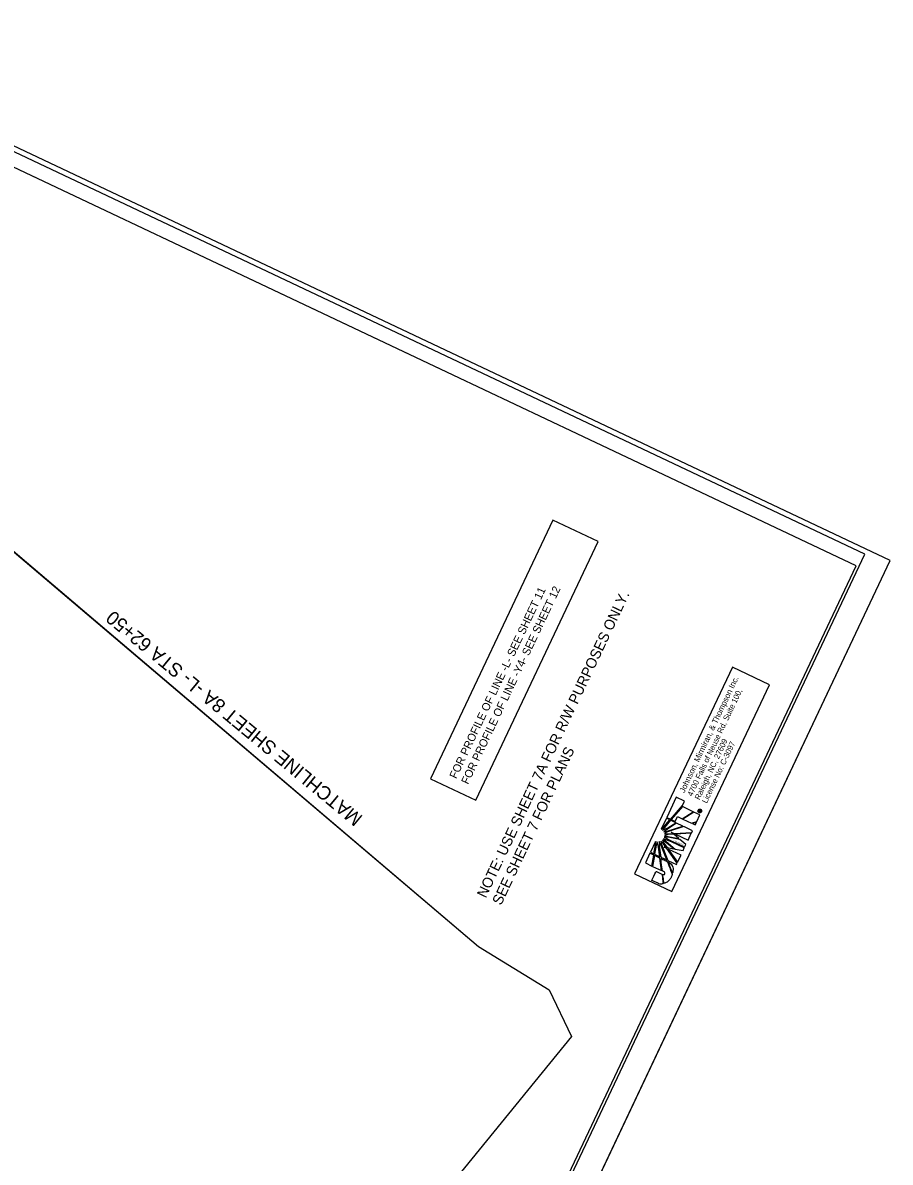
# Model space of a CAD drawing. Extents: x 556536 to 558250, y 505355 to 507347.
# Drawn here: x 557491 to 558250, y 506351 to 507347 of the extents above; entities that cross this region are included whole.
import ezdxf

# ---------------------------------------------------------------- set-up
doc = ezdxf.new("R2010")
doc.units = 0
for name, color, linetype in [('Matchline', 7, 'Continuous'), ('Matchline Text', 7, 'Continuous'), ('Prop Horizontal Alignment Curve and Spiral Data', 7, 'Continuous'), ('Prop Horizontal Alignment Direction Label', 7, 'Continuous'), ('Prop SS Cut Line', 7, 'Continuous'), ('Prop SS Fill Line', 7, 'Continuous'), ('Scratch_Level_9', 7, 'Continuous'), ('Sheet Clip Boundary CELL', 7, 'Continuous')]:
    doc.layers.add(name, color=color, linetype=linetype)

msp = doc.modelspace()

# ---------------------------------------------------------------- linework, layer by layer
at = {"layer": 'Matchline'}
for p, q in [((557395.12, 506959.79), (557889.73, 506539.36)), ((558062.8, 506670.04), (558054.41, 506652.24)), ((558070.09, 506666.6), (558062.8, 506670.04)), ((558057.77, 506650.65), (558068.31, 506662.82)), ((558068.21, 506661.77), (558058.28, 506650.42)), ((558077.55, 506657.36), (558068.21, 506661.77)), ((558068.31, 506662.82), (558070.09, 506666.6)), ((558081.91, 506658.68), (558082.18, 506658.56)), ((558082.18, 506658.56), (558081.91, 506658.68)), ((558082.42, 506657.79), (558082.67, 506658.32)), ((558082.67, 506658.32), (558082.71, 506658.41)), ((558082.67, 506658.32), (558082.92, 506658.21)), ((558082.92, 506658.21), (558082.67, 506658.32)), ((558082.92, 506658.21), (558082.81, 506657.97)), ((558082.81, 506657.97), (558083.11, 506657.83)), ((558082.93, 506658.24), (558082.92, 506658.21)), ((558083.11, 506657.83), (558083.22, 506658.06)), ((558083.22, 506658.06), (558083.23, 506658.07)), ((558083.22, 506658.06), (558083.46, 506657.95)), ((558083.46, 506657.95), (558083.22, 506658.06)), ((558083.46, 506657.95), (558083.35, 506657.72)), ((558083.47, 506657.96), (558083.46, 506657.95)), ((558054.14, 506651.56), (558049.67, 506642.19)), ((558051.91, 506644.04), (558057.18, 506650.13)), ((558057.83, 506649.83), (558052.41, 506643.52)), ((558057.18, 506650.13), (558054.14, 506651.56)), ((558054.41, 506652.24), (558057.67, 506650.7)), ((558057.67, 506650.7), (558057.77, 506650.65)), ((558062.29, 506647.65), (558057.83, 506649.83)), ((558058.28, 506650.42), (558058.33, 506650.39)), ((558058.33, 506650.39), (558061.74, 506648.78)), ((558061.74, 506648.78), (558063.79, 506653.13)), ((558063.79, 506653.13), (558067.86, 506651.21)), ((558067.86, 506651.21), (558077.55, 506657.36)), ((558078.21, 506657.05), (558068.55, 506650.88)), ((558068.55, 506650.88), (558076.13, 506647.31)), ((558076.13, 506647.31), (558080.76, 506648.83)), ((558080.36, 506648), (558076.95, 506646.92)), ((558083.46, 506654.58), (558078.21, 506657.05)), ((558079.33, 506645.8), (558080.36, 506648)), ((558080.76, 506648.83), (558083.46, 506654.58)), ((558083.72, 506657.18), (558082.42, 506657.79)), ((558083.35, 506657.72), (558083.85, 506657.48)), ((558083.85, 506657.48), (558083.72, 506657.18)), ((558084.47, 506657.47), (558084.48, 506657.49)), ((558084.47, 506657.47), (558084.75, 506657.34)), ((558084.75, 506657.34), (558084.47, 506657.47)), ((558084.76, 506657.35), (558084.75, 506657.34)), ((558049.67, 506642.19), (558051.91, 506644.04)), ((558052.41, 506643.52), (558050.84, 506641.06)), ((558050.84, 506641.06), (558055.42, 506643.24)), ((558054.98, 506642.2), (558051.81, 506639.7)), ((558051.81, 506639.7), (558054.91, 506640.24)), ((558055.15, 506639.66), (558052.36, 506638.23)), ((558052.36, 506638.23), (558055.56, 506637.98)), ((558054.91, 506640.24), (558068.46, 506644.74)), ((558063.04, 506647.3), (558054.98, 506642.2)), ((558069.34, 506644.33), (558055.15, 506639.66)), ((558055.42, 506643.24), (558062.29, 506647.65)), ((558055.56, 506637.98), (558059.78, 506638.21)), ((558059.78, 506638.21), (558058.31, 506639.44)), ((558058.31, 506639.44), (558060.78, 506638.27)), ((558060.78, 506638.27), (558076.24, 506639.25)), ((558075.87, 506638.57), (558062, 506637.7)), ((558068.46, 506644.74), (558063.04, 506647.3)), ((558076.94, 506640.74), (558069.34, 506644.33)), ((558073.01, 506632.51), (558075.87, 506638.57)), ((558076.24, 506639.25), (558076.94, 506640.74)), ((558076.95, 506646.92), (558079.33, 506645.8)), ((558044.58, 506631.41), (558040.09, 506621.88)), ((558043.12, 506620.45), (558044.51, 506628.47)), ((558045.17, 506628.16), (558043.78, 506620.14)), ((558044.51, 506628.47), (558044.58, 506631.41)), ((558046.14, 506631.08), (558045.17, 506628.16)), ((558047.34, 506626.23), (558046.14, 506631.08)), ((558049.3, 506628.45), (558047.78, 506631.16)), ((558047.78, 506631.16), (558047.89, 506627.17)), ((558049.26, 506631.66), (558049.93, 506628.59)), ((558051.49, 506629.35), (558049.26, 506631.66)), ((558054.38, 506615.14), (558049.3, 506628.45)), ((558049.93, 506628.59), (558055.28, 506614.72)), ((558050.59, 506632.52), (558051.95, 506629.83)), ((558053.09, 506631.05), (558050.59, 506632.52)), ((558053.88, 506626.05), (558051.49, 506629.35)), ((558058.48, 506630.95), (558051.63, 506633.74)), ((558051.63, 506633.74), (558053.79, 506631.3)), ((558051.95, 506629.83), (558054.78, 506625.91)), ((558052.28, 506635.14), (558058.76, 506631.56)), ((558055.52, 506634.98), (558052.28, 506635.14)), ((558055.47, 506637.29), (558052.55, 506636.67)), ((558052.55, 506636.67), (558055.39, 506635.67)), ((558060.51, 506624.87), (558053.09, 506631.05)), ((558053.79, 506631.3), (558061.82, 506624.6)), ((558055.39, 506635.67), (558064.97, 506633.83)), ((558060.47, 506637.61), (558055.47, 506637.29)), ((558065.96, 506633.03), (558055.52, 506634.98)), ((558069.77, 506625.63), (558058.48, 506630.95)), ((558058.76, 506631.56), (558070.05, 506626.23)), ((558064.97, 506633.83), (558060.47, 506637.61)), ((558062, 506637.7), (558073.01, 506632.51)), ((558071.16, 506628.58), (558065.96, 506633.03)), ((558070.05, 506626.23), (558071.16, 506628.58)), ((558039.72, 506620.98), (558035.72, 506612.51)), ((558042.99, 506619.44), (558039.72, 506620.98)), ((558040.09, 506621.88), (558043.12, 506620.45)), ((558041.34, 506609.86), (558042.99, 506619.44)), ((558043.6, 506619.15), (558041.98, 506609.56)), ((558048.51, 506616.84), (558043.6, 506619.15)), ((558043.78, 506620.14), (558048.36, 506617.98)), ((558048.36, 506617.98), (558047.34, 506626.23)), ((558047.89, 506627.17), (558049.1, 506617.63)), ((558054.38, 506625.3), (558052.14, 506626.36)), ((558052.14, 506626.36), (558053.88, 506626.05)), ((558063.62, 506612.49), (558054.38, 506625.3)), ((558054.78, 506625.91), (558060.51, 506624.87)), ((558066.91, 506619.46), (558055.59, 506624.73)), ((558055.59, 506624.73), (558063.93, 506613.15)), ((558061.82, 506624.6), (558068.67, 506623.31)), ((558063.93, 506613.15), (558066.91, 506619.46)), ((558068.67, 506623.31), (558069.77, 506625.63)), ((558035.72, 506612.51), (558041.34, 506609.86)), ((558041.98, 506609.56), (558049.88, 506605.84)), ((558049.88, 506605.84), (558048.51, 506616.84)), ((558049.1, 506617.63), (558054.38, 506615.14)), ((558055.28, 506614.72), (558062.96, 506611.09)), ((558062.96, 506611.09), (558063.62, 506612.49))]:
    msp.add_line(p, q, dxfattribs=at)
msp.add_lwpolyline([(558058.95, 506587.53), (558144.43, 506768.39), (558111.79, 506783.81), (558026.31, 506602.96)], close=True, dxfattribs=at)
for points in [[(558062.8, 506670.04), (558054.41, 506652.24), (558057.67, 506650.7), (558057.77, 506650.65), (558068.31, 506662.82), (558070.09, 506666.6), (558062.8, 506670.04)], [(558058.28, 506650.42), (558058.33, 506650.39), (558061.74, 506648.78), (558063.79, 506653.13), (558067.86, 506651.21), (558077.55, 506657.36), (558068.21, 506661.77), (558058.28, 506650.42)], [(558083.93, 506658.42), (558084, 506658.39), (558084.05, 506658.38), (558084.1, 506658.36), (558084.25, 506658.32), (558084.13, 506658.05)], [(558051.91, 506644.04), (558057.18, 506650.13), (558054.14, 506651.56), (558049.67, 506642.19), (558051.91, 506644.04)], [(558050.84, 506641.06), (558055.42, 506643.24), (558062.29, 506647.65), (558057.83, 506649.83), (558052.41, 506643.52), (558050.84, 506641.06)], [(558068.55, 506650.88), (558076.13, 506647.31), (558080.76, 506648.83), (558083.46, 506654.58), (558078.21, 506657.05), (558068.55, 506650.88), (558068.55, 506650.88)], [(558079.33, 506645.8), (558079.33, 506645.8), (558080.36, 506648), (558076.95, 506646.92), (558079.33, 506645.8)], [(558051.81, 506639.7), (558054.91, 506640.24), (558068.46, 506644.74), (558063.04, 506647.3), (558054.98, 506642.2), (558051.81, 506639.7)], [(558052.36, 506638.23), (558055.56, 506637.98), (558059.78, 506638.21), (558058.31, 506639.44), (558060.78, 506638.27), (558076.24, 506639.25), (558076.94, 506640.74), (558069.34, 506644.33), (558055.15, 506639.66), (558052.36, 506638.23)], [(558073.01, 506632.51), (558075.87, 506638.57), (558062, 506637.7), (558073.01, 506632.51)], [(558044.51, 506628.47), (558044.58, 506631.41), (558040.09, 506621.88), (558043.12, 506620.45), (558044.51, 506628.47)], [(558043.78, 506620.14), (558048.36, 506617.98), (558047.34, 506626.23), (558046.14, 506631.08), (558045.17, 506628.16), (558043.78, 506620.14)], [(558049.1, 506617.63), (558054.38, 506615.14), (558049.3, 506628.45), (558047.78, 506631.16), (558047.89, 506627.17), (558049.1, 506617.63)], [(558049.26, 506631.66), (558049.93, 506628.59), (558055.28, 506614.72), (558062.96, 506611.09), (558063.62, 506612.49), (558054.38, 506625.3), (558052.14, 506626.36), (558053.88, 506626.05), (558051.49, 506629.35), (558049.26, 506631.66)], [(558050.59, 506632.52), (558051.95, 506629.83), (558054.78, 506625.91), (558060.51, 506624.87), (558053.09, 506631.05), (558050.59, 506632.52)], [(558053.79, 506631.3), (558061.82, 506624.6), (558068.67, 506623.31), (558069.77, 506625.63), (558058.48, 506630.95), (558051.63, 506633.74), (558053.79, 506631.3)], [(558052.28, 506635.14), (558058.76, 506631.56), (558070.05, 506626.23), (558071.16, 506628.58), (558065.96, 506633.03), (558055.52, 506634.98), (558052.28, 506635.14)], [(558052.55, 506636.67), (558055.39, 506635.67), (558064.97, 506633.83), (558060.47, 506637.61), (558055.47, 506637.29), (558052.55, 506636.67)], [(558041.34, 506609.86), (558042.99, 506619.44), (558039.72, 506620.98), (558035.72, 506612.51), (558041.34, 506609.86)], [(558049.88, 506605.84), (558048.51, 506616.84), (558043.6, 506619.15), (558041.98, 506609.56), (558049.88, 506605.84)], [(558063.93, 506613.15), (558066.91, 506619.46), (558055.59, 506624.73), (558063.93, 506613.15)]]:
    msp.add_lwpolyline(points, dxfattribs=at)
for points, degree in [([(558084.75, 506657.34), (558084.57, 506656.95), (558084.27, 506656.68), (558083.85, 506656.53), (558083.45, 506656.37), (558083.04, 506656.39), (558082.64, 506656.58), (558082.24, 506656.77), (558081.97, 506657.07), (558081.84, 506657.48), (558081.7, 506657.89), (558081.72, 506658.28), (558081.91, 506658.68)], 3), ([(558081.91, 506658.68), (558082.09, 506659.08), (558082.4, 506659.36), (558082.8, 506659.51), (558083.19, 506659.67), (558083.6, 506659.65), (558084, 506659.47)], 3), ([(558082.18, 506658.56), (558082.03, 506658.24), (558082.01, 506657.92), (558082.11, 506657.59), (558082.23, 506657.27), (558082.46, 506657.01), (558082.77, 506656.86), (558083.09, 506656.71), (558083.43, 506656.7), (558083.76, 506656.82), (558084.09, 506656.94), (558084.32, 506657.16), (558084.47, 506657.47)], 3), ([(558084.48, 506657.49), (558084.63, 506657.8), (558084.65, 506658.12), (558084.53, 506658.45), (558084.41, 506658.78), (558084.19, 506659.03), (558083.87, 506659.18), (558083.55, 506659.33), (558083.21, 506659.35), (558082.88, 506659.23), (558082.57, 506659.11), (558082.33, 506658.89), (558082.18, 506658.56)], 3), ([(558082.71, 506658.41), (558082.87, 506658.73), (558083.07, 506658.84), (558083.33, 506658.72), (558083.45, 506658.66), (558083.52, 506658.57), (558083.54, 506658.43)], 3), ([(558083.23, 506658.07), (558083.32, 506658.26), (558083.3, 506658.38), (558083.2, 506658.43), (558083.1, 506658.48), (558083.02, 506658.42), (558082.93, 506658.24)], 3), ([(558083.62, 506658.16), (558083.58, 506658.14), (558083.52, 506658.08), (558083.47, 506657.96)], 2), ([(558083.54, 506658.43), (558083.63, 506658.49), (558083.76, 506658.49), (558083.93, 506658.42)], 2), ([(558084.13, 506658.05), (558084.04, 506658.05), (558083.96, 506658.06), (558083.86, 506658.11), (558083.75, 506658.16), (558083.67, 506658.18), (558083.62, 506658.16)], 3), ([(558084, 506659.47), (558084.4, 506659.28), (558084.68, 506658.97), (558084.83, 506658.57), (558084.97, 506658.16), (558084.95, 506657.75), (558084.76, 506657.35)], 3), ([(558052.73, 506603.01), (558052.49, 506602.51), (558052.01, 506602.2), (558050.99, 506602.46), (558050.99, 506602.46), (558051.88, 506594.61), (558051.88, 506594.61), (558054.73, 506595.56), (558057.32, 506597.99), (558058.51, 506600.52), (558058.82, 506601.18), (558059, 506601.71), (558059.19, 506602.47), (558059.19, 506602.47), (558054.9, 506613.82), (558054.9, 506613.82), (558054.9, 506613.82), (558049.2, 506616.51), (558049.2, 506616.51), (558049.2, 506616.51), (558050.59, 506605.5), (558050.59, 506605.5), (558052.73, 506604.49), (558053.06, 506603.71), (558052.73, 506603.01)], 3), ([(558052.73, 506603.01), (558052.49, 506602.51), (558052.01, 506602.2), (558050.99, 506602.46), (558050.99, 506602.46), (558051.88, 506594.61), (558051.88, 506594.61), (558054.73, 506595.56), (558057.32, 506597.99), (558058.51, 506600.52), (558058.82, 506601.18), (558059, 506601.71), (558059.19, 506602.47), (558059.19, 506602.47), (558054.9, 506613.82), (558054.9, 506613.82), (558054.9, 506613.82), (558049.2, 506616.51), (558049.2, 506616.51), (558049.2, 506616.51), (558050.59, 506605.5), (558050.59, 506605.5), (558052.73, 506604.49), (558053.06, 506603.71), (558052.73, 506603.01)], 3), ([(558055.8, 506613.4), (558055.8, 506613.4), (558059.49, 506603.59), (558059.49, 506603.59), (558060.22, 506607.2), (558059.6, 506611.42), (558055.8, 506613.4)], 3), ([(558045.1, 506605.12), (558045.1, 506605.12), (558041.4, 506597.28), (558041.4, 506597.28), (558041.4, 506597.28), (558046.31, 506594.97), (558046.31, 506594.97), (558046.31, 506594.97), (558046.83, 506594.73), (558046.83, 506594.73), (558048.36, 506594), (558049.81, 506593.93), (558051.26, 506594.34), (558051.26, 506594.34), (558050.38, 506602.63), (558050.28, 506602.68), (558050.28, 506602.68), (558045.1, 506605.12), (558045.1, 506605.12)], 3)]:
    msp.add_open_spline(points, degree=degree, dxfattribs=at)
at = {"layer": 'Prop Horizontal Alignment Curve and Spiral Data'}
msp.add_lwpolyline([(557847.78, 506686.21), (557887.58, 506667.4), (557994.48, 506893.58), (557954.69, 506912.39), (557847.78, 506686.21)], dxfattribs=at)
at = {"layer": 'Prop Horizontal Alignment Direction Label'}
msp.add_lwpolyline([(557255.37, 507347.15), (556535.75, 505824.65), (557530.26, 505354.59), (558249.88, 506877.09)], close=True, dxfattribs=at)
at = {"layer": 'Prop SS Cut Line'}
msp.add_lwpolyline([(557270.71, 507321.1), (556629.72, 505964.95), (557579.02, 505516.26), (558220.01, 506872.41)], close=True, dxfattribs=at)
at = {"layer": 'Prop SS Fill Line'}
msp.add_lwpolyline([(557273.74, 507333.49), (556561.61, 505826.81), (557515.52, 505375.94), (558227.66, 506882.62)], close=True, dxfattribs=at)
at = {"layer": 'Scratch_Level_9'}
msp.add_line((557530.26, 505354.59), (558249.88, 506877.09), dxfattribs=at)
at = {"layer": 'Sheet Clip Boundary CELL'}
msp.add_lwpolyline([(557803.27, 506254.64), (557635.29, 505993.61), (557687.24, 505840.99), (557643.42, 505687.13), (557512.37, 505750.31), (557008.7, 505860.07), (556630.15, 505965.86), (557185.22, 507140.23), (557323.61, 507073.55), (557367.3, 507166.35), (557435.08, 507139.34), (557448.32, 507074.91), (557453.98, 507069.78), (557474.03, 506970.73), (557395.12, 506959.79), (557425.46, 506933.59), (557889.73, 506539.36), (557951.72, 506501.53), (557971.08, 506460.75)], close=True, dxfattribs=at)

# ---------------------------------------------------------------- texts
at = {"layer": 'Matchline'}
for s, height, rotation, p in [('Johnson, Mirmiran, & Thompson Inc.', 5.1112, 64.7021, (558069.87, 506673.49)), ('4700 Falls of Neuse Rd, Suite 100, ', 4.9652, 64.7021, (558076.65, 506670.28)), ('Raleigh, NC, 27609', 4.9652, 64.7021, (558083.07, 506667.25)), ('License No: C-3097', 4.9652, 64.7021, (558089.48, 506664.22)), ('www.jmt.com', 1.2413, 334.7021, (558060.18, 506631.58))]:
    msp.add_text(s, height=height, rotation=rotation, dxfattribs=at).set_placement(p)
at = {"layer": 'Matchline Text'}
msp.add_text('MATCHLINE SHEET 8A -L- STA 62+50', height=12, rotation=140.41535, dxfattribs=at).set_placement((557789.25, 506653.01))
at = {"layer": 'Prop Horizontal Alignment Curve and Spiral Data'}
for s, height, p in [('FOR PROFILE OF LINE -L- SEE SHEET 11', 7, (557870.31, 506685.61)), ('FOR PROFILE OF LINE -Y4- SEE SHEET 12', 7, (557880.6, 506680.75)), ('NOTE: USE SHEET 7A FOR R/W PURPOSES ONLY.', 9.1, (557896.18, 506581.27)), ('SEE SHEET 7 FOR PLANS', 9.1, (557909.55, 506574.95))]:
    msp.add_text(s, height=height, rotation=64.7021, dxfattribs=at).set_placement(p)

doc.saveas('drawing.dxf')
